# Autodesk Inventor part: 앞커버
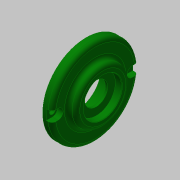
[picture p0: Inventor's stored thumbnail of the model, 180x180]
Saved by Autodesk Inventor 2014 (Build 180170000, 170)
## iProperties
Created: 2019-06
Part Number: 앞커버
Material: 알루미늄 6061
Document SubType Name: Modeling
Designer: mduedu
Density: 1 g/cm^3
Appearance: 진녹색
Author: mduedu
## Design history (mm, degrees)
sketch "스케치1"
  geometry: L1 (0, 0)-(7, 0); L2 (7, 0)-(7, 25); L3 (7, 25)-(0, 25); L4 (0, 25)-(0, 0); L5 (7, 0)-(14, 0); L6 (14, 0)-(14, 34); L7 (14, 34)-(7, 34); L8 (7, 34)-(7, 0); L9 (14, 0)-(20, 0); L10 (20, 0)-(20, 21); L11 (20, 21)-(14, 21); L12 (14, 21)-(14, 0)
  constraints: 24 end point, 6 parallel, 3 horizontal, 3 perpendicular
  dimensions: "d0" = 20 distance between parallel lines of L10 L4; "d2" = 7 distance of L2.end L3.end; "d3" = 7 distance of L6.end L7.end; "d4" = 50 diameter of L3 L1; "d5" = 68 diameter of L7 L5; "d6" = 42 diameter of L11 L9
revolve "회전1" sketch "스케치1" stored, may be unused: angle "d7" = 90 deg
sketch "스케치2"
  geometry: L1 (0, -25)-(0, 25) reference; L2 (0, 25)-(7, 25) reference; L3 (7, 25)-(7, 34) reference; L4 (7, 34)-(14, 34) reference; L5 (14, 34)-(14, 21) reference; L6 (14, 21)-(20, 21) reference; L7 (20, 21)-(20, -21) reference; L8 (20, -21)-(14, -21) reference; L9 (14, -21)-(14, -34) reference; L10 (14, -34)-(7, -34) reference; L11 (7, -34)-(7, -25) reference; L12 (7, -25)-(0, -25) reference; L13 (10, 0)-(10, 17.5); L14 (10, 17.5)-(0, 17.5); L15 (0, 17.5)-(0, 0); L16 (13, 0)-(13, 15); L17 (13, 15)-(10, 15); L18 (10, 15)-(10, 0); L19 (14.8, 0)-(14.8, 9); L20 (14.8, 9)-(13, 9); L21 (13, 9)-(13, 0); L22 (20, 0)-(20, 15); L23 (20, 15)-(14.8, 15); L24 (14.8, 15)-(14.8, 0)
  constraints: 24 end point, 4 horizontal, 4 horizontal alignment, 4 parallel, 4 vertical, 1 point on line, 8 other
  dimensions: "d8" = 35 dimension on L14; "d10" = 30 dimension on L17; "d11" = 18 dimension on L20; "d12" = 30 dimension on L23; "d13" = 10 distance of L13.end L14.end; "d14" = 3 distance of L16.end L17.end; "d15" = 5.2 distance of L22.end L23.end
revolve "회전2" sketch "스케치2" stored, may be unused: angle "d16" = 90 deg
chamfer "모따기1" distance "d18" = 0.5; stored, may be unused: second distance "d19" = 2, angle "d20" = 30 deg
fillet "모깎기2" dims "d21" = 0.3
fillet "모깎기3" dims "d22" = 3
chamfer "모따기2" distance "d23" = 1; stored, may be unused: second distance "d24" = 2, angle "d25" = 30 deg
fillet "모깎기4" dims "d26" = 3
sketch "스케치3" dims "d27" = 58
  geometry: L1 (-4, 29)-(-4, 33.764); L2 (4, 33.764)-(4, 29); A1 r 4 centre (0, 29) between (-4, 29) and (4, 29); A2 r 34 centre (0, 0) between (4, 33.764) and (-4, 33.764); A3 r 34 centre (0, 0) between (4, 33.764) and (-4, 33.764) reference; 3 further points
  constraints: 6 point on circle, 4 end point, 3 coincident, 2 centre point, 2 tangent, 2 vertical, 2 vertical alignment, 1 concentric, 2 other
  dimensions: "d28" = 8 diameter of A1
extrude "돌출1" cut sketch "스케치3" distance "d29" = 4.4; taper "d30" = 0 deg
sketch "스케치4"
  geometry: A1 r 4 centre (0, 29) between (-4, 29) and (4, 29) reference; 2 further points
  constraints: 1 coincident
hole "구멍1" sketch "스케치4" at (0, 29) diameter "d34" = 4.5; stored, may be unused: countersink angle "d38" = 90 deg, drill point angle "d40" = 118 deg; dims "d35" = 6, "d36" = 4, "d37" = 2, "d39" = 8
node "솔리드1"
pattern_circular "원형 패턴1" dims angle "d32" = 360 deg
pattern_circular "원형 패턴2" dims angle "d42" = 360 deg
node "절단 모서리 투영1"
